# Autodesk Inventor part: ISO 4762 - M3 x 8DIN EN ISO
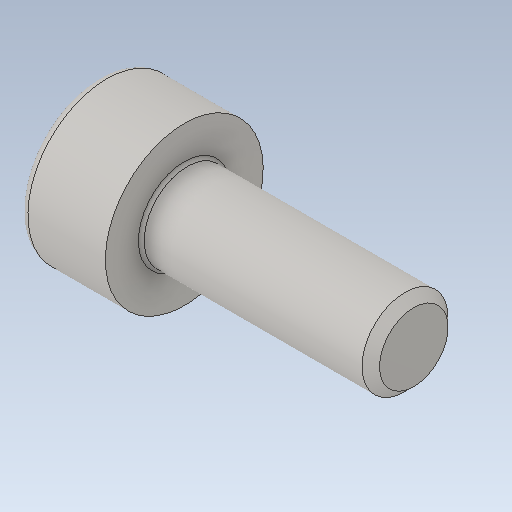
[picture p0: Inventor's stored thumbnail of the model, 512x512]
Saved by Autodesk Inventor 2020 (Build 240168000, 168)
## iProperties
Created: 2017-11
Part Number: ISO 4762 - M3 x 8DIN EN ISO
Material: Ogólny
Document SubType Name: Modeling
Designer: Tomasz
Density: 1 g/cm^3
Appearance: Domyślna
Sending System: SolidWorks 2017
Last Author: Tomasz
Last Saved: 2017-11-19
Author: Tomasz
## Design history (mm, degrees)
feature "ISO 4762 - M3 x 8DIN EN ISO.ipt"
node "Bryła1"
